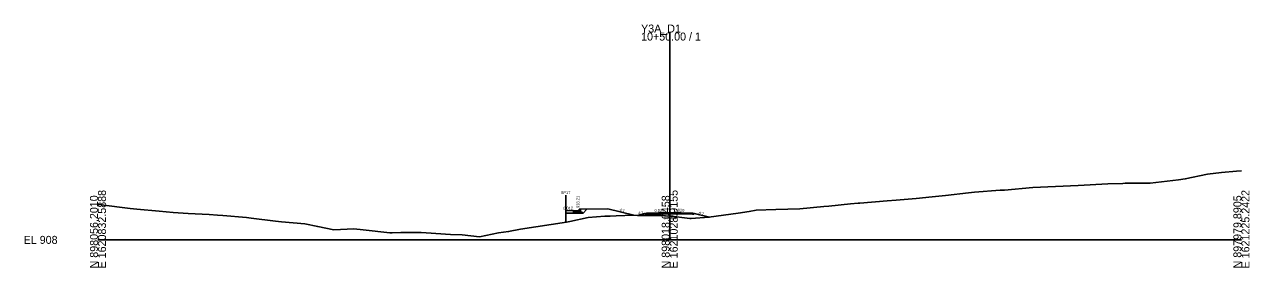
# Model space of a CAD drawing. Extents: x -12685 to 1621059, y -3463 to 898072.
# Drawn here: x -12685.4 to -12256.9, y -2963 to -2877.8 of the extents above; entities that cross this region are included whole.
import ezdxf

# ---------------------------------------------------------------- set-up
doc = ezdxf.new("R2010")
doc.units = 0
for name, color, linetype in [('Exist Cross Section Cell', 7, 'Continuous'), ('Exist XS Center Line Elevation Label', 7, 'Continuous'), ('Exist XS Ground Line', 7, 'Continuous'), ('Old_Level_63', 7, 'Continuous'), ('Prop CMT Pvmt Course 2', 7, 'Continuous'), ('Prop CMT Pvmt Gravel', 7, 'Continuous'), ('Prop CMT Slope Grass', 7, 'Continuous'), ('Prop CMT Subgrade Earthwork', 7, 'Continuous'), ('Prop XS Earthwork Shape', 7, 'Continuous'), ('Prop XS Label Text', 7, 'Continuous'), ('Prop XS SE Text', 7, 'Continuous'), ('Prop XS Shear Point Label', 7, 'Continuous'), ('Prop XS Side Slope Text', 7, 'Continuous')]:
    doc.layers.add(name, color=color, linetype=linetype)

msp = doc.modelspace()

# ---------------------------------------------------------------- linework, layer by layer
at = {"layer": 'Exist Cross Section Cell'}
for p, q in [((-12459.75, -2953.26), (-12459.75, -2880.63)), ((-12659.75, -2953.26), (-12459.75, -2953.26)), ((-12459.75, -2953.26), (-12259.75, -2953.26))]:
    msp.add_line(p, q, dxfattribs=at)
at = {"layer": 'Exist XS Ground Line'}
msp.add_lwpolyline([(-12659.75, -2940.85), (-12658.62, -2940.97), (-12648.54, -2942.26), (-12646.1, -2942.48), (-12638.35, -2943.25), (-12633.46, -2943.64), (-12628.16, -2943.97), (-12620.81, -2944.36), (-12617.97, -2944.61), (-12616.06, -2944.77), (-12607.79, -2945.42), (-12606.19, -2945.61), (-12597.6, -2946.73), (-12595.52, -2946.89), (-12587.41, -2947.66), (-12582.88, -2948.58), (-12577.22, -2949.69), (-12570.23, -2949.42), (-12567.03, -2949.69), (-12557.59, -2950.76), (-12556.85, -2950.74), (-12553.78, -2950.7), (-12546.66, -2950.63), (-12544.94, -2950.83), (-12536.47, -2951.35), (-12532.3, -2951.47), (-12526.29, -2952.2), (-12519.65, -2950.8), (-12516.1, -2950.36), (-12511.89, -2949.47), (-12495.9, -2947.03), (-12494.71, -2946.81), (-12488.21, -2945.43), (-12482.4, -2945), (-12480.61, -2944.91), (-12478.44, -2944.84), (-12472.33, -2944.65), (-12466.74, -2944.74), (-12462.63, -2944.76), (-12459.75, -2944.92), (-12458.63, -2944.99), (-12458.2, -2945.03), (-12454.53, -2945.54), (-12452.71, -2945.8), (-12452.21, -2945.76), (-12446.03, -2945.34), (-12435.76, -2943.9), (-12431.96, -2943.3), (-12429.53, -2942.89), (-12422.59, -2942.64), (-12414.22, -2942.35), (-12405.85, -2941.6), (-12404.03, -2941.46), (-12396.52, -2940.69), (-12393.85, -2940.43), (-12393.2, -2940.37), (-12383.66, -2939.6), (-12380.56, -2939.34), (-12373.47, -2938.75), (-12367.91, -2938.17), (-12363.28, -2937.71), (-12355.27, -2936.78), (-12353.1, -2936.56), (-12344.1, -2935.9), (-12342.62, -2935.8), (-12332.72, -2934.95), (-12316.81, -2934.2), (-12306.47, -2933.68), (-12301.23, -2933.51), (-12300.45, -2933.45), (-12291.68, -2933.37), (-12281.78, -2932.23), (-12279.4, -2931.89), (-12271.6, -2930.2), (-12266.75, -2929.7), (-12261.41, -2929.21), (-12259.75, -2929.05)], dxfattribs=at)
at = {"layer": 'Old_Level_63'}
msp.add_line((-12496.1, -2943.94), (-12496.1, -2947.06), dxfattribs=at)
at = {"layer": 'Prop CMT Pvmt Course 2'}
for points in [[(-12467.75, -2944.27), (-12459.75, -2944.11)], [(-12451.75, -2944.27), (-12459.75, -2944.11)]]:
    msp.add_lwpolyline(points, dxfattribs=at)
at = {"layer": 'Prop CMT Pvmt Gravel'}
for points in [[(-12467.75, -2943.85), (-12468.19, -2944.28)], [(-12459.75, -2943.69), (-12467.75, -2943.85)], [(-12459.75, -2943.69), (-12451.75, -2943.85)], [(-12451.75, -2943.85), (-12451.32, -2944.28)]]:
    msp.add_lwpolyline(points, dxfattribs=at)
at = {"layer": 'Prop CMT Slope Grass'}
for p, q in [((-12467.75, -2943.85), (-12471.05, -2944.67)), ((-12467.75, -2943.85), (-12459.75, -2943.69)), ((-12459.75, -2943.69), (-12451.75, -2943.85)), ((-12451.75, -2943.85), (-12445.87, -2945.32))]:
    msp.add_line(p, q, dxfattribs=at)
at = {"layer": 'Prop CMT Subgrade Earthwork'}
for points in [[(-12467.75, -2944.27), (-12468.19, -2944.28), (-12468.45, -2944.02)], [(-12459.75, -2944.11), (-12467.75, -2944.27)], [(-12459.75, -2944.11), (-12451.75, -2944.27)], [(-12451.75, -2944.27), (-12451.32, -2944.28), (-12451.06, -2944.02)]]:
    msp.add_lwpolyline(points, dxfattribs=at)
at = {"layer": 'Prop XS Earthwork Shape'}
for points in [[(-12471.05, -2944.67), (-12466.74, -2944.74), (-12462.63, -2944.76), (-12459.75, -2944.92), (-12458.63, -2944.99), (-12458.2, -2945.03), (-12454.53, -2945.54), (-12452.71, -2945.8), (-12452.21, -2945.76), (-12446.03, -2945.34), (-12445.87, -2945.32), (-12451.06, -2944.02), (-12451.32, -2944.28), (-12451.75, -2944.27), (-12459.75, -2944.11), (-12467.75, -2944.27), (-12468.19, -2944.28), (-12468.45, -2944.02)], [(-12468.45, -2944.02), (-12471.05, -2944.67), (-12466.74, -2944.74), (-12462.63, -2944.76), (-12459.75, -2944.92), (-12458.63, -2944.99), (-12458.2, -2945.03), (-12454.53, -2945.54), (-12452.71, -2945.8), (-12452.21, -2945.76), (-12446.03, -2945.34), (-12445.87, -2945.32), (-12451.06, -2944.02), (-12451.32, -2944.28), (-12451.75, -2944.27), (-12459.75, -2944.11), (-12467.75, -2944.27), (-12468.19, -2944.28)]]:
    msp.add_lwpolyline(points, close=True, dxfattribs=at)
at = {"layer": 'Prop XS Label Text'}
msp.add_line((-12496.1, -2937.65), (-12496.1, -2947.06), dxfattribs=at)
at = {"layer": 'Prop XS Shear Point Label'}
for p, q in [((-12496.1, -2943.94), (-12496.1, -2943.03)), ((-12490.89, -2942.55), (-12481.39, -2942.36)), ((-12481.39, -2942.36), (-12472.25, -2944.65))]:
    msp.add_line(p, q, dxfattribs=at)
for points in [[(-12496.1, -2943.03), (-12493.39, -2943)], [(-12496.1, -2943.94), (-12493.33, -2943.91)], [(-12493.39, -2943.91), (-12490.06, -2943.87), (-12488.7, -2942.51)], [(-12493.39, -2943), (-12491.39, -2943.05), (-12491.39, -2942.55), (-12490.89, -2942.55)], [(-12490.89, -2942.55), (-12490.89, -2943.55), (-12493.39, -2943.58)], [(-12493.39, -2943.58), (-12493.39, -2943)], [(-12493.39, -2943), (-12491.39, -2943.05)], [(-12493.39, -2943.58), (-12490.39, -2943.54), (-12490.06, -2943.87)], [(-12493.39, -2943.91), (-12493.39, -2943.58)], [(-12490.06, -2943.87), (-12493.39, -2943.91)], [(-12491.39, -2943.05), (-12491.39, -2942.55), (-12490.89, -2942.55)]]:
    msp.add_lwpolyline(points, dxfattribs=at)

# ---------------------------------------------------------------- texts
at = {"layer": 'Exist Cross Section Cell'}
for s, p in [('Y3A_D1', (-12469.75, -2880.63)), ('10+50.00 / 1', (-12469.75, -2883.43)), ('EL 908', (-12685.75, -2954.66))]:
    msp.add_text(s, height=2.8, dxfattribs=at).set_placement(p)
for s, p in [('N 898056.2010', (-12659.75, -2963.26)), ('E 1620832.5888', (-12656.95, -2963.26)), ('N 898018.0458', (-12459.75, -2963.26)), ('E 1621028.9155', (-12456.95, -2963.26)), ('N 897979.8905', (-12259.75, -2963.26)), ('E 1621225.2422', (-12256.95, -2963.26))]:
    msp.add_text(s, height=2.8, rotation=90, dxfattribs=at).set_placement(p)
at = {"layer": 'Exist XS Center Line Elevation Label'}
msp.add_text('916.34', height=1, dxfattribs=at).set_placement((-12461.77, -2946.12))
at = {"layer": 'Prop XS SE Text'}
for rotation, p in [(1.1458, (-12465.05, -2943.5)), (358.8542, (-12458.08, -2943.34))]:
    msp.add_text('0.020', height=1, rotation=rotation, dxfattribs=at).set_placement(p)
at = {"layer": 'Prop XS Shear Point Label'}
for s, rotation, p in [('SP17', 0, (-12497.86, -2937.23)), ('918.21', 90, (-12491.35, -2942.06)), ('0.012', 0.6758, (-12497, -2942.68)), ('4:1', 345.9638, (-12477.39, -2943.13))]:
    msp.add_text(s, height=1, rotation=rotation, dxfattribs=at).set_placement(p)
at = {"layer": 'Prop XS Side Slope Text'}
for rotation, p in [(14.0362, (-12470.63, -2944.44)), (345.9638, (-12449.72, -2944.24))]:
    msp.add_text('4:1', height=1, rotation=rotation, dxfattribs=at).set_placement(p)

doc.saveas('drawing.dxf')
